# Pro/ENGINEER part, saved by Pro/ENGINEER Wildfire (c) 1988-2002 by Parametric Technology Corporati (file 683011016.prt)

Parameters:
  DESCRIPTION = "CUSTOM HEADER .100/(2.54) CENTERLINE VERTICAL/SMT SINGLE ROW "
  MATERIAL = "NYLON 46, GLASS FILLED, UL 94V-0, COLOR:BLACK"
  SERIES_NO = "68301"
  REVISION = "M1"
  DOCUMENT_CONTROL = "68301"

Other parameters: NO_OF_CKTS

Family table entries: ENDIF, IF , D645, D705, D655, D678, D710, D707, d791, d792, $D668, D668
